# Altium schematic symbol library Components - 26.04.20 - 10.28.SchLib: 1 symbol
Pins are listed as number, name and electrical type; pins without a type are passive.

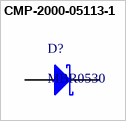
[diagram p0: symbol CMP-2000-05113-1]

## CMP-2000-05113-1
designator D?, comment MBR0530
Diode Schottky 30V 0.5A 2-Pin SOD-123 T/R; Manufacturer: Fairchild; Speed: FastRecovery=200mA(Io); Voltage - Forward (Vf) (Max) @ If: 430mV@500mA; Online Catalog: SchottkyDiode; Current - Reverse Leakage @ Vr: 130µA@30V; Current - Average Rectified (Io): 500mA; Other Names: MBR0530CT
footprint FAIR-SOD123-2_V (SOD123, 2-Leads, Body 1.80x2.85mm)
pins: 1 A, 2 K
